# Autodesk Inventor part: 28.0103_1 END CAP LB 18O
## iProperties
Created: 2007-01
Part Number: 28.0103_1 END CAP LB 18O
Document SubType Name: Modeling
Designer: Andy Moles
Material: ABS Plastic
Density: 1.06 g/cm^3
Author: Andy Moles
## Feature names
1. Extrusion1
2. Fillet1
3. Fillet2
4. Extrusion2
